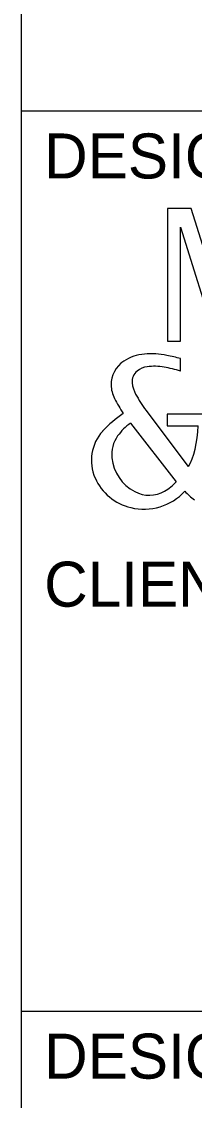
# Model space of a CAD drawing. Extents: x -6.6 to 34, y 0 to 22.
# Drawn here: x 32 to 32.383, y 2.302 to 4.699 of the extents above; entities that cross this region are included whole.
import ezdxf

# ---------------------------------------------------------------- set-up
doc = ezdxf.new("R2010")
doc.units = 0
for name, color, linetype in [('SH_Border', 7, 'Continuous'), ('SH_Data', 7, 'Continuous'), ('SH_Text', 7, 'Continuous')]:
    doc.layers.add(name, color=color, linetype=linetype)

msp = doc.modelspace()

# ---------------------------------------------------------------- linework, layer by layer
at = {"layer": 'SH_Border'}
for p, q in [((32, 0.5), (32, 21.5)), ((32, 4.5), (33.5, 4.5)), ((32, 2.5), (33.5, 2.5))]:
    msp.add_line(p, q, dxfattribs=at)
at = {"layer": 'SH_Data'}
for p, q in [((32.3525, 3.922), (32.3525, 3.9497)), ((32.37, 3.7101), (32.2762, 3.8349)), ((32.1797, 3.7884), (32.18, 3.7887)), ((32.2416, 3.8065), (32.3429, 3.6759))]:
    msp.add_line(p, q, dxfattribs=at)
msp.add_lwpolyline([(32.3526, 3.9885), (32.3527, 4.2417), (32.4317, 3.9885), (32.4542, 3.9885), (32.536, 4.2417), (32.5359, 3.9885), (32.5784, 3.9885), (32.5785, 4.2831), (32.5246, 4.2831), (32.4495, 4.0504), (32.3765, 4.2832), (32.3235, 4.2832), (32.3234, 3.9886)], close=True, dxfattribs=at)
msp.add_lwpolyline([(32.3526, 3.9885), (32.3527, 4.2417), (32.4317, 3.9885), (32.4542, 3.9885), (32.536, 4.2417), (32.5359, 3.9885), (32.5784, 3.9885), (32.5785, 4.2831), (32.5246, 4.2831), (32.4495, 4.0504), (32.3765, 4.2832), (32.3235, 4.2832), (32.3234, 3.9886)], close=True, dxfattribs=at)
msp.add_lwpolyline([(32.4211, 3.8006), (32.6049, 3.8006), (32.6049, 3.8261), (32.3233, 3.8261), (32.3233, 3.8007), (32.3916, 3.8006)], dxfattribs=at)
for centre, radius, start, end in [((32.2803, 3.862), 0.0981, 94.5206, 123.1061), ((32.2871, 3.7753), 0.1851, 79.0563, 94.5206), ((32.2546, 3.6069), 0.3566, 74.0516, 79.0563), ((32.2606, 3.8922), 0.062, 123.1061, 181.2152), ((32.2855, 3.8851), 0.0471, 98.3723, 128.329), ((32.2951, 3.8196), 0.1132, 79.2666, 98.3723), ((32.2746, 3.8989), 0.0295, 128.329, 186.0821), ((32.2495, 3.579), 0.3581, 73.2803, 79.2666), ((32.2669, 3.8924), 0.0684, 181.2152, 207.1091), ((32.3115, 3.9028), 0.0666, 186.0821, 208.5769), ((32.517, 4.0204), 0.3493, 207.1091, 213.4656), ((32.5116, 4.0118), 0.2945, 208.5769, 216.933), ((32.3628, 3.6213), 0.2479, 123.6, 137.6035), ((32.2512, 3.7236), 0.0964, 137.6035, 203.9313), ((32.3108, 3.7092), 0.1194, 125.3927, 144.9042), ((32.2717, 3.7366), 0.0717, 144.9042, 185.7554), ((32.2959, 3.7391), 0.096, 185.7554, 242.1528), ((32.2691, 3.7316), 0.116, 203.9313, 256.6813), ((32.2633, 3.7491), 0.1081, 299.979, 317.3992), ((32.271, 3.7399), 0.1246, 256.6813, 317.1089), ((32.2831, 3.7148), 0.0685, 242.1528, 299.979), ((32.487, 3.7702), 0.1697, 222.685, 232.3525)]:
    msp.add_arc(centre, radius, start, end, dxfattribs=at)
msp.add_ellipse((32.351, 3.8018), major_axis=(-0.0031, -0.1077), ratio=0.377453, start_param=0.562501, end_param=1.570796, dxfattribs=at)

# ---------------------------------------------------------------- texts
for s, p in [('DESIGN AGENCY', (32.05, 4.35)), ('DESIGNER', (32.05, 2.35))]:
    msp.add_text(s, height=0.1, dxfattribs=at).set_placement(p)
at = {"layer": 'SH_Text'}
msp.add_text('CLIENT', height=0.1, dxfattribs=at).set_placement((32.05, 3.3986))

doc.saveas('drawing.dxf')
